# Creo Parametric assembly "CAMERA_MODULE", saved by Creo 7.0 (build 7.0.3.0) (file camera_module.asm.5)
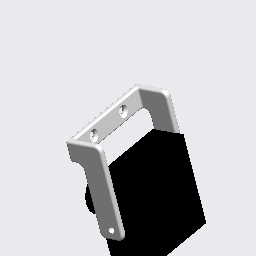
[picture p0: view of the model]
Units: millimeter Kilogram Sec (mmKs); MM, KILOGRAM, SECS

Created from: XX_MMKS_ASM_DESIGN_ABS.ASM

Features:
  1. datum plane "ASM_RIGHT"
  2. datum plane "ASM_TOP"
  3. datum plane "ASM_FRONT"
  4. coordinate system
  5. component "CAMERA_SET"
  6. component "CAMERA"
